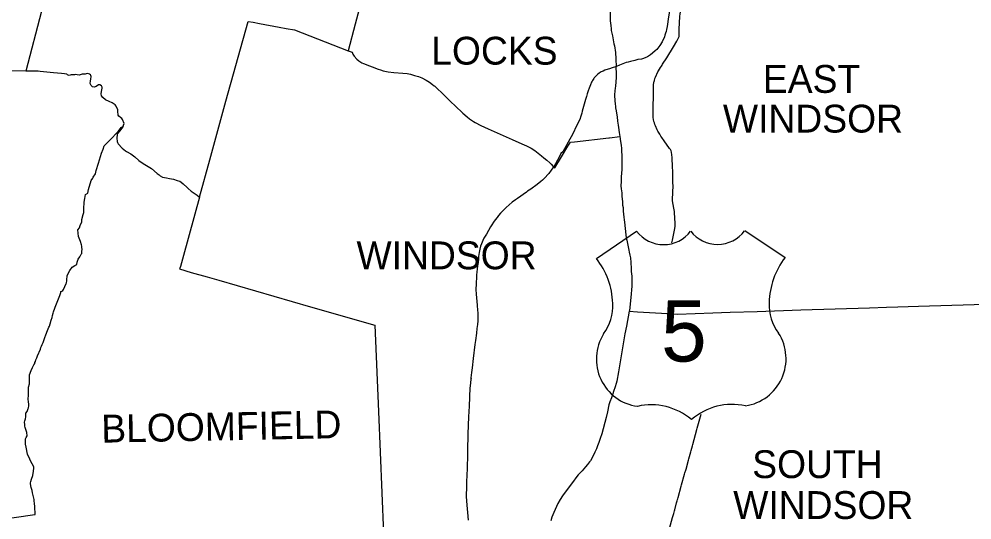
# Model space of a CAD drawing. Extents: x 0 to 2603, y -226 to 830.
# Drawn here: x 185.31 to 231.48, y 653.45 to 677.73 of the extents above; entities that cross this region are included whole.
import ezdxf

# ---------------------------------------------------------------- set-up
doc = ezdxf.new("R2010")
doc.units = 0
for name, color, linetype in [('CT_TSH_Map_Districts', 7, 'Continuous'), ('CT_TSH_Map_Interstate_Roads', 7, 'Continuous'), ('CT_TSH_Map_Town_Limits', 7, 'Continuous'), ('CT_TSH_Map_Town_Text', 7, 'Continuous'), ('CT_TSH_Map_US_and_State_Routes', 7, 'Continuous')]:
    doc.layers.add(name, color=color, linetype=linetype)

msp = doc.modelspace()

# ---------------------------------------------------------------- linework, layer by layer
at = {"layer": 'CT_TSH_Map_Districts'}
for points in [[(202.846, 682.232), (202.23, 679.895), (202.138, 679.551), (201.594, 677.485), (201.253, 676.198)], [(194.062, 669.105), (194.554, 670.915), (195.337, 673.751), (196.411, 677.609), (196.65, 677.575), (196.969, 677.514), (197.922, 677.348), (198.257, 677.282), (198.65, 677.213), (201.253, 676.198)], [(188.249, 666.202), (188.329, 666.334), (188.359, 666.373), (188.356, 666.46), (188.363, 666.585), (188.359, 666.666), (188.347, 666.72), (188.331, 666.785), (188.283, 666.944), (188.193, 667.199), (188.155, 667.515), (188.235, 667.615), (188.275, 667.726), (188.346, 667.9), (188.359, 668.023), (188.417, 668.25), (188.45, 668.348), (188.443, 668.527), (188.464, 668.857), (188.497, 669.039), (188.524, 669.231), (188.648, 669.289), (188.677, 669.469), (188.813, 669.912), (188.884, 670.016), (188.905, 670.06), (189.016, 670.232), (189.052, 670.388), (189.16, 670.752), (189.311, 671.226), (189.383, 671.429), (189.436, 671.595), (189.581, 671.729), (189.703, 671.859), (190.106, 672.288), (190.267, 672.472), (190.349, 672.541)], [(190.349, 672.541), (190.293, 672.447), (190.177, 672.297), (190.077, 672.183), (190.061, 672.138), (190.047, 671.965), (190.064, 671.792), (190.08, 671.747), (190.112, 671.685), (190.313, 671.482), (190.464, 671.342), (190.521, 671.316), (190.734, 671.201), (190.914, 671.052), (191.108, 670.877), (191.332, 670.731), (191.732, 670.493), (192.005, 670.251), (192.103, 670.184), (192.153, 670.14), (192.259, 670.075), (192.457, 670.032), (192.604, 670.011), (192.797, 669.965), (192.967, 669.914), (193.095, 669.868), (193.16, 669.828), (193.256, 669.749), (193.458, 669.563), (193.499, 669.52), (193.651, 669.396), (193.946, 669.189), (194.062, 669.105)], [(183.403, 653.32), (185.968, 653.7), (186.099, 653.713), (186.072, 654.103), (186.056, 654.241), (186.05, 654.375), (186.041, 654.438), (185.969, 654.759), (185.948, 654.871), (185.906, 655.021), (185.87, 655.203), (185.87, 655.252), (185.884, 655.314), (185.922, 655.42), (185.972, 655.602), (186.015, 655.81), (186.03, 655.956), (186.032, 655.997), (186.028, 656.02), (185.866, 656.32), (185.834, 656.391), (185.714, 656.633), (185.651, 656.978), (185.628, 657.13), (185.625, 657.374), (185.654, 657.444), (185.701, 657.528), (185.685, 657.688), (185.603, 657.939), (185.592, 657.988), (185.585, 658.074), (185.583, 658.194), (185.591, 658.256), (185.631, 658.35), (185.642, 658.442), (185.638, 658.621), (185.711, 658.71), (185.748, 658.855), (185.765, 658.888), (185.783, 658.978), (185.786, 659.027), (185.77, 659.207), (185.756, 659.276), (185.754, 659.342), (185.767, 659.464), (185.772, 659.713), (185.77, 659.857), (185.772, 659.894), (185.821, 660.045), (185.824, 660.104), (185.811, 660.427), (185.818, 660.453), (185.82, 660.481), (185.899, 660.695), (185.956, 660.835), (186.024, 660.969), (186.07, 661.041), (186.078, 661.085), (186.103, 661.138), (186.125, 661.205), (186.172, 661.301), (186.205, 661.398), (186.347, 661.734), (186.371, 661.802), (186.406, 661.877), (186.43, 661.952), (186.456, 662.012), (186.476, 662.05), (186.545, 662.241), (186.558, 662.288), (186.615, 662.418), (186.688, 662.64), (186.752, 662.796), (186.785, 662.85), (186.816, 662.951), (186.868, 663.143), (186.908, 663.267), (186.933, 663.362), (186.972, 663.479), (186.988, 663.543), (187.051, 663.721), (187.064, 663.771), (187.284, 664.332), (187.336, 664.48), (187.344, 664.519), (187.382, 664.541), (187.431, 664.577), (187.473, 664.614), (187.598, 664.906), (187.616, 664.951), (187.62, 665.041), (187.622, 665.078), (187.636, 665.306), (187.772, 665.538), (187.879, 665.704), (188.007, 665.781), (188.052, 665.808), (188.114, 665.84), (188.133, 665.948), (188.171, 666.09), (188.249, 666.202)]]:
    msp.add_lwpolyline(points, dxfattribs=at)
at = {"layer": 'CT_TSH_Map_Interstate_Roads'}
for points in [[(216.827, 678.154), (216.796, 677.925), (216.78, 677.838), (216.708, 677.374)], [(216.708, 677.374), (216.682, 677.226), (216.661, 677.13), (216.636, 677.045), (216.606, 676.951), (216.577, 676.878), (216.469, 676.626)], [(216.362, 676.453), (216.309, 676.387), (216.207, 676.256), (216.13, 676.189)], [(216.469, 676.626), (216.362, 676.453)], [(215.681, 675.875), (215.561, 675.825), (215.461, 675.793), (215.293, 675.766), (215.142, 675.728)], [(215.904, 676.004), (215.754, 675.91), (215.681, 675.875)], [(216.13, 676.189), (216.115, 676.181), (215.904, 676.004)], [(214.397, 675.497), (214.372, 675.488), (214.206, 675.425), (214.047, 675.368)], [(214.727, 675.623), (214.397, 675.497)], [(214.819, 675.646), (214.74, 675.627), (214.727, 675.623)], [(214.941, 675.676), (214.819, 675.646)], [(215.142, 675.728), (214.941, 675.676)], [(213.355, 675.063), (213.323, 675.034), (213.267, 674.98), (213.219, 674.928), (213.181, 674.884), (213.155, 674.847), (213.12, 674.798), (213.098, 674.761), (213.074, 674.722), (213.046, 674.668), (212.995, 674.539), (212.937, 674.38), (212.892, 674.252)], [(213.466, 675.144), (213.419, 675.112), (213.355, 675.063)], [(213.604, 675.211), (213.516, 675.176), (213.466, 675.144)], [(213.859, 675.304), (213.7, 675.249), (213.604, 675.211)], [(213.925, 675.328), (213.859, 675.304)], [(214.047, 675.368), (213.925, 675.328)], [(212.892, 674.252), (212.844, 674.106), (212.8, 673.973), (212.758, 673.828)], [(212.758, 673.828), (212.599, 673.274)], [(212.573, 673.176), (212.535, 673.027)], [(212.599, 673.274), (212.573, 673.176)], [(212.476, 672.87), (212.293, 672.499)], [(212.535, 673.027), (212.476, 672.87)], [(212.172, 672.232), (212.068, 672.021)], [(212.293, 672.499), (212.172, 672.232)], [(211.998, 671.905), (211.65, 671.297)], [(212.068, 672.021), (211.998, 671.905)], [(211.65, 671.297), (211.564, 671.208), (211.524, 671.128)], [(211.406, 670.899), (211.302, 670.712), (211.215, 670.572)], [(211.524, 671.128), (211.406, 670.899)], [(211.179, 670.519), (211.097, 670.401), (210.971, 670.24)], [(211.215, 670.572), (211.179, 670.519)], [(210.752, 670.006), (210.672, 669.928), (210.587, 669.852), (210.419, 669.718), (210.102, 669.493)], [(210.971, 670.24), (210.752, 670.006)], [(210.102, 669.493), (209.952, 669.384)], [(209.46, 669.036), (209.368, 668.973), (209.209, 668.849), (209.065, 668.733), (208.909, 668.593), (208.762, 668.447), (208.643, 668.318), (208.545, 668.209), (208.473, 668.118), (208.378, 667.996), (208.293, 667.879), (208.22, 667.765), (208.156, 667.654), (208.062, 667.485)], [(209.952, 669.384), (209.892, 669.347), (209.46, 669.036)], [(207.923, 667.249), (207.837, 667.108), (207.779, 666.994), (207.712, 666.836), (207.673, 666.73), (207.629, 666.572), (207.598, 666.419), (207.575, 666.226), (207.572, 666.084)], [(207.961, 667.31), (207.923, 667.249)], [(208.062, 667.485), (207.961, 667.31)], [(207.572, 666.084), (207.552, 665.971), (207.511, 665.644)], [(207.482, 665.354), (207.47, 665.212), (207.453, 664.922), (207.447, 664.596), (207.458, 664.426), (207.474, 664.187)], [(207.511, 665.644), (207.489, 665.441), (207.482, 665.354)], [(207.474, 664.187), (207.483, 664.071), (207.499, 663.828), (207.523, 663.637), (207.535, 663.477), (207.539, 663.291), (207.536, 663.108), (207.524, 662.923), (207.498, 662.734)], [(207.498, 662.734), (207.468, 662.504), (207.422, 662.154)], [(207.422, 662.154), (207.392, 661.948), (207.313, 661.278), (207.262, 660.824)], [(207.262, 660.824), (207.237, 660.596), (207.208, 660.342), (207.212, 660.315)], [(207.212, 660.315), (207.201, 660.282), (207.167, 659.943)], [(207.154, 659.849), (207.115, 658.96)], [(207.167, 659.943), (207.154, 659.849)], [(207.115, 658.96), (207.095, 658.455), (207.077, 658.038), (207.062, 657.609), (207.055, 657.341)], [(207.044, 656.967), (207.037, 656.742)], [(207.055, 657.341), (207.046, 657.092), (207.044, 656.967)], [(207.034, 656.626), (207.015, 655.943)], [(207.037, 656.742), (207.034, 656.626)], [(207.015, 655.943), (206.996, 655.29)], [(206.996, 655.29), (206.987, 654.929), (206.979, 654.741), (206.976, 654.61)], [(206.976, 654.61), (206.996, 654.361), (207.075, 653.442)]]:
    msp.add_lwpolyline(points, dxfattribs=at)
at = {"layer": 'CT_TSH_Map_Town_Limits'}
for points in [[(189.648, 691.09), (189.449, 690.267), (189.186, 689.181), (188.982, 688.394), (188.956, 688.263), (188.664, 687.046), (188.49, 686.362), (188.433, 686.107), (187.978, 684.293), (187.827, 683.666), (187.295, 681.525), (186.94, 680.138), (186.403, 678.111), (185.648, 675.21)], [(202.846, 682.232), (202.23, 679.895), (202.138, 679.551), (201.594, 677.485), (201.253, 676.198)], [(213.95, 678.189), (213.956, 677.643), (213.989, 677.42), (214.007, 677.254), (214.007, 677.172), (214.057, 676.914), (214.131, 676.528), (214.157, 676.431), (214.201, 676.105), (214.208, 676.074), (214.223, 675.836), (214.222, 675.712), (214.224, 675.692), (214.234, 675.528), (214.23, 675.286), (214.238, 675.209), (214.236, 674.899), (214.204, 674.476), (214.185, 674.379), (214.178, 674.251), (214.162, 674.055), (214.164, 673.955), (214.173, 673.843), (214.18, 673.726), (214.187, 673.692), (214.209, 673.431), (214.242, 673.284), (214.272, 673.075), (214.289, 672.994), (214.307, 672.775), (214.333, 672.596), (214.351, 672.484), (214.382, 672.233), (214.412, 672.037)], [(194.062, 669.105), (194.554, 670.915), (195.337, 673.751), (196.411, 677.609), (196.65, 677.575), (196.969, 677.514), (197.922, 677.348), (198.257, 677.282), (198.65, 677.213), (201.253, 676.198)], [(201.253, 676.198), (201.443, 676.123), (201.487, 676.036), (201.551, 675.937), (201.674, 675.794), (201.77, 675.711), (201.924, 675.61), (202.003, 675.574), (202.283, 675.469), (202.427, 675.413), (202.709, 675.301), (202.819, 675.268), (202.955, 675.218), (203.198, 675.171), (203.471, 675.141), (203.903, 675.11), (204.116, 675.089), (204.276, 675.059), (204.476, 675.003), (204.659, 674.945), (204.831, 674.877), (205.041, 674.766), (205.199, 674.666), (205.337, 674.564), (205.418, 674.497), (205.454, 674.473), (205.93, 674.027), (205.99, 673.961), (206.149, 673.809), (206.233, 673.719), (206.444, 673.525), (206.811, 673.177), (207.027, 672.99), (207.143, 672.901), (207.334, 672.771), (207.405, 672.726), (207.692, 672.578), (208.045, 672.407), (209.2, 671.898), (209.677, 671.681), (209.904, 671.583), (210.118, 671.479), (210.297, 671.365), (210.628, 671.104), (210.737, 671.01), (210.883, 670.893), (211.02, 670.758), (211.096, 670.692), (211.193, 670.593), (211.267, 670.526), (211.544, 670.97), (211.9, 671.569), (212.021, 671.764), (212.222, 671.788), (213.878, 671.967), (213.912, 671.977), (214.412, 672.037)], [(185.648, 675.21), (184.735, 675.218), (184.209, 675.231), (183.528, 675.237), (183.011, 675.247), (181.68, 675.274), (181.469, 675.274), (181.15, 675.278), (180.182, 675.321), (178.581, 675.409), (178.267, 675.418), (174.92, 675.576), (173.584, 675.646), (170.104, 675.781), (169.628, 675.794)], [(190.349, 672.541), (190.374, 672.59), (190.398, 672.675), (190.326, 672.861), (190.288, 672.92), (190.229, 672.957), (190.138, 673.031), (190.113, 673.076), (190.102, 673.273), (190.094, 673.333), (190.022, 673.504), (189.97, 673.575), (189.82, 673.674), (189.679, 673.739), (189.508, 673.825), (189.367, 673.929), (189.306, 674.008), (189.294, 674.112), (189.299, 674.22), (189.338, 674.38), (189.333, 674.425), (189.311, 674.493), (189.229, 674.546), (189.164, 674.538), (189.046, 674.466), (188.957, 674.439), (188.878, 674.445), (188.799, 674.505), (188.763, 674.611), (188.777, 674.74), (188.796, 674.826), (188.805, 674.943), (188.793, 674.997), (188.769, 675.032), (188.723, 675.068), (188.641, 675.09), (188.557, 675.076), (188.513, 675.059), (188.43, 675.067), (188.369, 675.063), (188.229, 675.012), (188.13, 675.034), (188.038, 675.04), (187.991, 675.035), (187.835, 675.036), (187.746, 675.004), (187.694, 675.011), (187.662, 675.031), (187.629, 675.067), (187.521, 675.077), (187.364, 675.088), (186.983, 675.126), (186.332, 675.189), (186.237, 675.204), (186, 675.204), (185.648, 675.21)], [(188.249, 666.202), (188.329, 666.334), (188.359, 666.373), (188.356, 666.46), (188.363, 666.585), (188.359, 666.666), (188.347, 666.72), (188.331, 666.785), (188.283, 666.944), (188.193, 667.199), (188.155, 667.515), (188.235, 667.615), (188.275, 667.726), (188.346, 667.9), (188.359, 668.023), (188.417, 668.25), (188.45, 668.348), (188.443, 668.527), (188.464, 668.857), (188.497, 669.039), (188.524, 669.231), (188.648, 669.289), (188.677, 669.469), (188.813, 669.912), (188.884, 670.016), (188.905, 670.06), (189.016, 670.232), (189.052, 670.388), (189.16, 670.752), (189.311, 671.226), (189.383, 671.429), (189.436, 671.595), (189.581, 671.729), (189.703, 671.859), (190.106, 672.288), (190.267, 672.472), (190.349, 672.541)], [(190.349, 672.541), (190.293, 672.447), (190.177, 672.297), (190.077, 672.183), (190.061, 672.138), (190.047, 671.965), (190.064, 671.792), (190.08, 671.747), (190.112, 671.685), (190.313, 671.482), (190.464, 671.342), (190.521, 671.316), (190.734, 671.201), (190.914, 671.052), (191.108, 670.877), (191.332, 670.731), (191.732, 670.493), (192.005, 670.251), (192.103, 670.184), (192.153, 670.14), (192.259, 670.075), (192.457, 670.032), (192.604, 670.011), (192.797, 669.965), (192.967, 669.914), (193.095, 669.868), (193.16, 669.828), (193.256, 669.749), (193.458, 669.563), (193.499, 669.52), (193.651, 669.396), (193.946, 669.189), (194.062, 669.105)], [(214.412, 672.037), (214.428, 671.939), (214.431, 671.887), (214.478, 671.622), (214.493, 671.463), (214.494, 671.404), (214.519, 671.039), (214.521, 670.997), (214.508, 670.656), (214.514, 670.477), (214.495, 670.236), (214.491, 670.117), (214.485, 670.06), (214.485, 669.943), (214.479, 669.866), (214.472, 669.643), (214.485, 669.501), (214.508, 669.316), (214.52, 669.191), (214.519, 669.154), (214.551, 668.876), (214.556, 668.705), (214.577, 668.603), (214.582, 668.414), (214.619, 668.134), (214.626, 668.003), (214.644, 667.891), (214.707, 667.275), (214.731, 667.129), (214.764, 667.006), (214.852, 666.523), (214.874, 666.439), (214.904, 666.28), (214.931, 666.155), (214.959, 665.929), (214.973, 665.638), (214.976, 665.495), (214.997, 665.275), (214.996, 665.138), (214.999, 665.095), (215.002, 664.813), (214.996, 664.764), (214.989, 664.621), (214.971, 664.397), (214.884, 663.597), (214.877, 663.569)], [(194.062, 669.105), (193.275, 666.266), (193.134, 665.738), (193.091, 665.621), (193.658, 665.45), (194.423, 665.237), (194.983, 665.082), (199.438, 663.783), (202.546, 662.885), (202.724, 658.701), (202.972, 652.787), (203.089, 650.147), (203.119, 649.389), (203.164, 648.163)], [(183.403, 653.32), (185.968, 653.7), (186.099, 653.713), (186.072, 654.103), (186.056, 654.241), (186.05, 654.375), (186.041, 654.438), (185.969, 654.759), (185.948, 654.871), (185.906, 655.021), (185.87, 655.203), (185.87, 655.252), (185.884, 655.314), (185.922, 655.42), (185.972, 655.602), (186.015, 655.81), (186.03, 655.956), (186.032, 655.997), (186.028, 656.02), (185.866, 656.32), (185.834, 656.391), (185.714, 656.633), (185.651, 656.978), (185.628, 657.13), (185.625, 657.374), (185.654, 657.444), (185.701, 657.528), (185.685, 657.688), (185.603, 657.939), (185.592, 657.988), (185.585, 658.074), (185.583, 658.194), (185.591, 658.256), (185.631, 658.35), (185.642, 658.442), (185.638, 658.621), (185.711, 658.71), (185.748, 658.855), (185.765, 658.888), (185.783, 658.978), (185.786, 659.027), (185.77, 659.207), (185.756, 659.276), (185.754, 659.342), (185.767, 659.464), (185.772, 659.713), (185.77, 659.857), (185.772, 659.894), (185.821, 660.045), (185.824, 660.104), (185.811, 660.427), (185.818, 660.453), (185.82, 660.481), (185.899, 660.695), (185.956, 660.835), (186.024, 660.969), (186.07, 661.041), (186.078, 661.085), (186.103, 661.138), (186.125, 661.205), (186.172, 661.301), (186.205, 661.398), (186.347, 661.734), (186.371, 661.802), (186.406, 661.877), (186.43, 661.952), (186.456, 662.012), (186.476, 662.05), (186.545, 662.241), (186.558, 662.288), (186.615, 662.418), (186.688, 662.64), (186.752, 662.796), (186.785, 662.85), (186.816, 662.951), (186.868, 663.143), (186.908, 663.267), (186.933, 663.362), (186.972, 663.479), (186.988, 663.543), (187.051, 663.721), (187.064, 663.771), (187.284, 664.332), (187.336, 664.48), (187.344, 664.519), (187.382, 664.541), (187.431, 664.577), (187.473, 664.614), (187.598, 664.906), (187.616, 664.951), (187.62, 665.041), (187.622, 665.078), (187.636, 665.306), (187.772, 665.538), (187.879, 665.704), (188.007, 665.781), (188.052, 665.808), (188.114, 665.84), (188.133, 665.948), (188.171, 666.09), (188.249, 666.202)], [(214.877, 663.569), (215.278, 663.543), (216.439, 663.482), (217.207, 663.433), (218.922, 663.489), (219.76, 663.52), (221.073, 663.557), (223.183, 663.63), (226.522, 663.732), (227.338, 663.762), (227.894, 663.775), (228.395, 663.794), (228.896, 663.807), (231.591, 663.896), (232.702, 663.937)], [(214.877, 663.569), (214.742, 662.85), (214.664, 662.472), (214.354, 660.629), (214.266, 660.173), (214.236, 660.069), (214.195, 659.91), (214.114, 659.679), (214.081, 659.563), (214.012, 659.374), (213.929, 659.181), (213.891, 659.025), (213.82, 658.684), (213.759, 658.413), (213.554, 657.632), (213.473, 657.397), (213.404, 657.2), (213.341, 657.045), (213.288, 656.895), (213.214, 656.732), (213.098, 656.491), (212.995, 656.323), (212.955, 656.267), (212.845, 656.142), (212.753, 656.024), (212.591, 655.832), (212.406, 655.629), (212.285, 655.484), (212.181, 655.335), (211.678, 654.67), (211.637, 654.611), (211.525, 654.444), (211.414, 654.245), (211.22, 653.81), (211.13, 653.577), (211.078, 653.408)]]:
    msp.add_lwpolyline(points, dxfattribs=at)
at = {"layer": 'CT_TSH_Map_US_and_State_Routes'}
for p, q in [((213.281, 666.127), (215.234, 667.443)), ((220.467, 667.475), (222.43, 666.169)), ((213.282, 666.129), (213.281, 666.127))]:
    msp.add_line(p, q, dxfattribs=at)
for points in [[(217.294, 677.117), (217.291, 677.237), (217.324, 677.86), (217.341, 677.991), (217.403, 678.299), (217.474, 678.572), (217.49, 678.636)], [(216.492, 675.541), (216.7, 675.851), (217.011, 676.381), (217.184, 676.661), (217.231, 676.757), (217.262, 676.82)], [(217.262, 676.82), (217.287, 676.887), (217.3, 676.992), (217.298, 677.042), (217.294, 677.117)], [(216.291, 675.231), (216.393, 675.388), (216.433, 675.451)], [(216.433, 675.451), (216.468, 675.505), (216.492, 675.541)], [(216.154, 674.924), (216.266, 675.175), (216.291, 675.231)], [(216.053, 674.404), (216.057, 674.541), (216.071, 674.653), (216.073, 674.668), (216.077, 674.699), (216.094, 674.753)], [(216.094, 674.753), (216.122, 674.858), (216.136, 674.888), (216.154, 674.924)], [(216.04, 673.314), (216.045, 674.178), (216.051, 674.334), (216.053, 674.404)], [(216.073, 672.768), (216.041, 672.953), (216.04, 673.249), (216.04, 673.314)], [(216.222, 672.365), (216.141, 672.551), (216.115, 672.626), (216.093, 672.7), (216.073, 672.768)], [(216.353, 672.149), (216.256, 672.298), (216.237, 672.335), (216.222, 672.365)], [(216.83, 671.464), (216.569, 671.823), (216.453, 671.986), (216.408, 672.06), (216.353, 672.149)], [(216.909, 671.34), (216.87, 671.402), (216.83, 671.464)], [(216.958, 671.025), (216.918, 671.283), (216.909, 671.34)], [(216.974, 670.625), (216.961, 670.952), (216.958, 671.025)], [(216.994, 669.754), (216.984, 670.244), (216.986, 670.352), (216.977, 670.558), (216.974, 670.625)], [(217.065, 668.401), (217.033, 668.559), (216.995, 668.741), (216.976, 668.927), (216.969, 668.993), (216.984, 669.317), (216.998, 669.66), (216.997, 669.682), (216.994, 669.754)], [(217.106, 667.844), (217.07, 668.335), (217.065, 668.401)], [(216.934, 666.889), (216.966, 667.016), (217.088, 667.573), (217.103, 667.685), (217.104, 667.776), (217.106, 667.844)], [(218.171, 657.894), (218.355, 658.572)], [(217.955, 657.111), (218.153, 657.829), (218.171, 657.894)], [(217.874, 656.821), (217.937, 657.046), (217.955, 657.111)], [(217.765, 656.42), (217.855, 656.754), (217.874, 656.821)], [(217.626, 655.919), (217.746, 656.353), (217.765, 656.42)], [(217.414, 655.156), (217.556, 655.666), (217.575, 655.734)], [(217.575, 655.734), (217.611, 655.866), (217.626, 655.919)], [(217.243, 654.534), (217.396, 655.091), (217.414, 655.156)], [(217.08, 653.945), (217.17, 654.28), (217.199, 654.378), (217.217, 654.44)], [(217.217, 654.44), (217.225, 654.471), (217.243, 654.534)], [(216.713, 652.622), (216.976, 653.567), (217.03, 653.762), (217.049, 653.831)], [(217.049, 653.831), (217.068, 653.899), (217.08, 653.945)]]:
    msp.add_lwpolyline(points, dxfattribs=at)
for centre, radius, start, end in [((216.535, 668.429), 1.632, 217.1377, 323.3979), ((219.153, 668.442), 1.632, 217.1377, 323.3979), ((210.355, 663.831), 3.722, 1.8086, 38.1428), ((225.375, 663.901), 3.722, 142.3929, 178.7271), ((211.847, 663.807), 2.232, 323.1742, 3.6193), ((223.883, 663.864), 2.232, 176.9164, 217.3614), ((220.165, 661.266), 2.308, 278.3979, 32.5975), ((215.589, 661.244), 2.308, 147.9382, 262.1377), ((215.94, 656.023), 3.009, 49.6665, 102.7966), ((219.863, 656.042), 3.009, 77.739, 130.8691)]:
    msp.add_arc(centre, radius, start, end, dxfattribs=at)

# ---------------------------------------------------------------- texts
at = {"layer": 'CT_TSH_Map_Town_Text'}
for s, p in [('LOCKS', (205.282, 675.525)), ('EAST', (221.349, 674.156)), ('WINDSOR', (219.413, 672.231)), ('WINDSOR', (201.661, 665.603)), ('SOUTH', (220.832, 655.478)), ('WINDSOR', (219.913, 653.496))]:
    msp.add_text(s, height=1.35, dxfattribs=at).set_placement(p)
msp.add_text('BLOOMFIELD', height=1.35, rotation=1.0989, dxfattribs=at).set_placement((189.307, 657.194))
at = {"layer": 'CT_TSH_Map_US_and_State_Routes'}
msp.add_text('5', height=2.971, dxfattribs=at).set_placement((216.418, 661.131))

doc.saveas('drawing.dxf')
